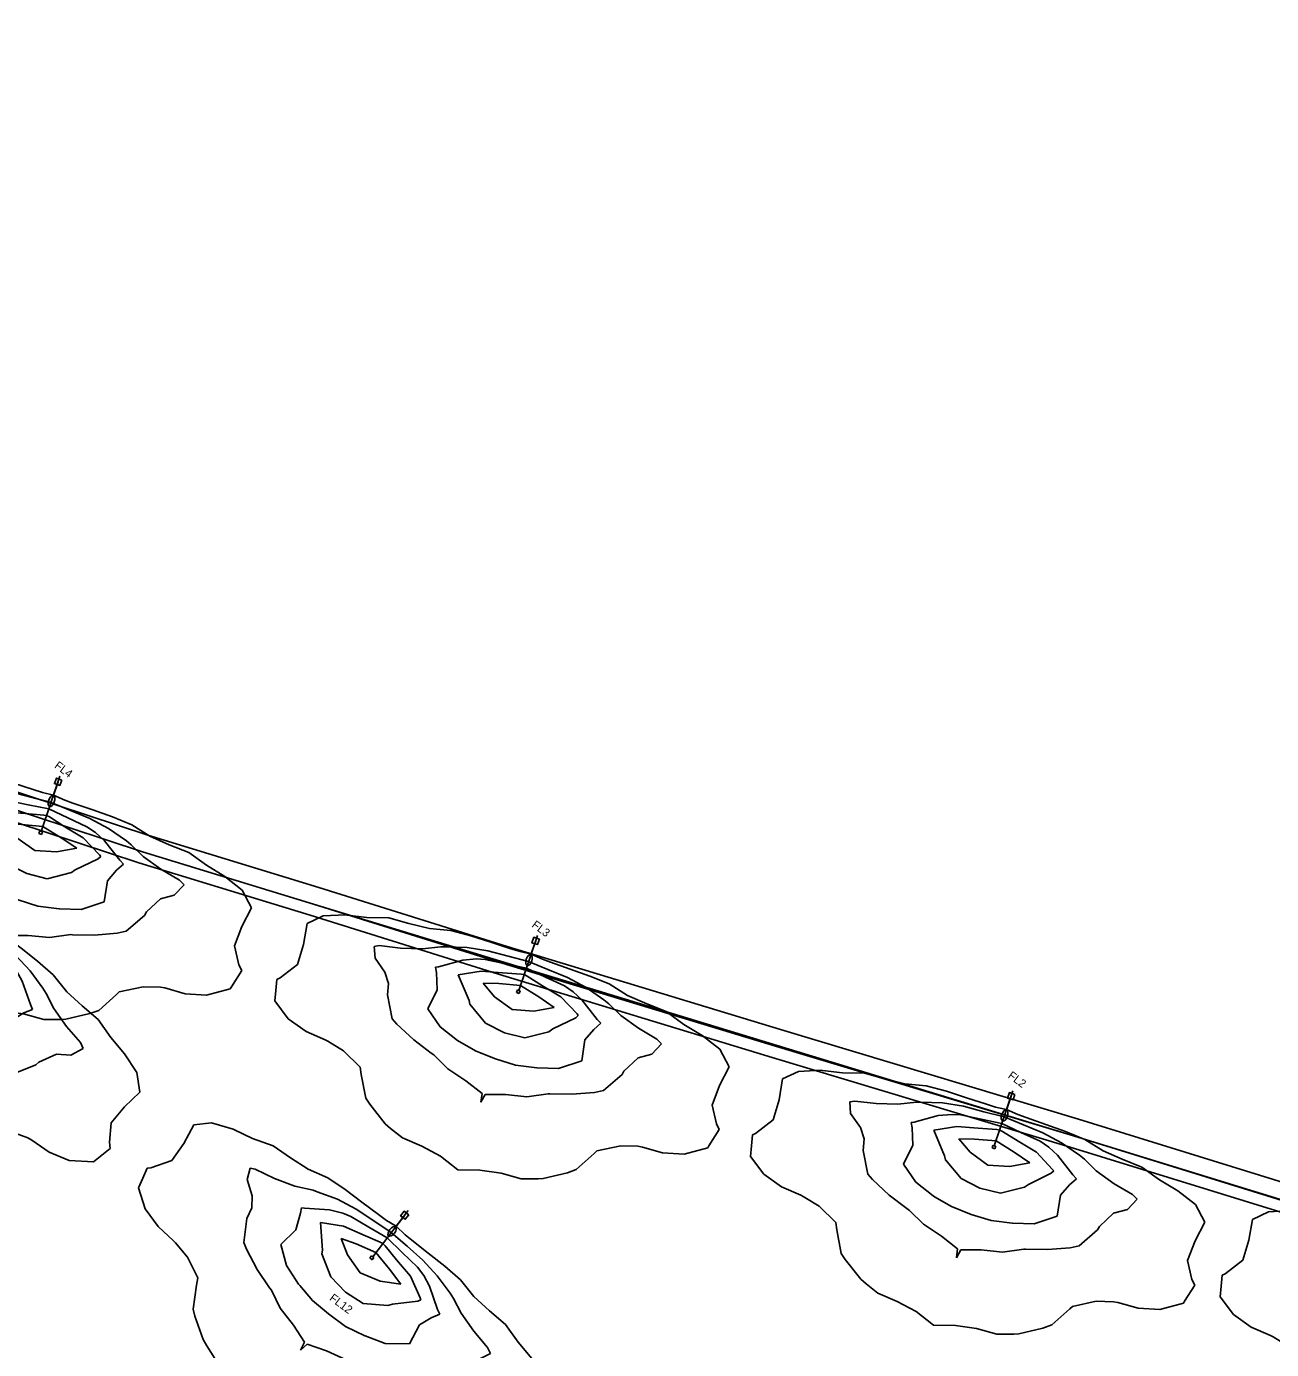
# Model space of a CAD drawing. Extents: x 1322666 to 1327584, y 458075 to 462260.
# Drawn here: x 1324729.9 to 1325158.3, y 460364.4 to 460819.6 of the extents above; entities that cross this region are included whole.
import ezdxf

# ---------------------------------------------------------------- set-up
doc = ezdxf.new("R2010")
doc.units = 0
for name, color, linetype in [('Default', 7, 'Continuous'), ('DR_P_Culvert', 7, 'Continuous'), ('DR_P_Culvert3D', 7, 'Continuous'), ('PF_X_Ground_Line', 7, 'Continuous'), ('UT_X_Misc_Cells', 7, 'Continuous')]:
    doc.layers.add(name, color=color, linetype=linetype)

# ---------------------------------------------------------------- blocks, each defined once
blk = doc.blocks.new('AGI32-IDj66arb-Project_1-LUMINAIRE-ERL2_19C330______Symbol')
at = {"layer": 'Default'}
for p, q in [((-0.03, 0), (0.03, 0)), ((0, 0.13), (0.24, 0.13)), ((0, -0.13), (0, 0.13)), ((0, 0.13), (0, 0.13)), ((0, 0.13), (0.24, 0.13)), ((0.24, 0.13), (0, 0.13)), ((0, -0.13), (0, 0.13)), ((0, 0.13), (0, 0.13)), ((0, 0.13), (0, -0.13)), ((0.24, 0.13), (0, 0.13)), ((0, 0.13), (0, -0.13)), ((0, -0.03), (0, 0.03)), ((0, 0.03), (0.03, 0)), ((0, -0.03), (0.03, 0)), ((0.24, 0.13), (0.24, -0.13)), ((0.24, 0.13), (0.24, 0.13)), ((0.24, 0.13), (0.24, 0.13)), ((0.24, 0.13), (0.24, -0.13)), ((0.24, -0.13), (0.24, 0.13)), ((0.24, -0.13), (0.24, 0.13)), ((0.24, -0.13), (0, -0.13)), ((0.24, -0.13), (0, -0.13)), ((0, -0.13), (0, -0.13)), ((0, -0.13), (0.24, -0.13)), ((0, -0.13), (0, -0.13)), ((0, -0.13), (0.24, -0.13)), ((0.24, -0.13), (0.24, -0.13)), ((0.24, -0.13), (0.24, -0.13))]:
    blk.add_line(p, q, dxfattribs=at)
blk = doc.blocks.new('AGI32-IDj66arb-Project_1-LUMINAIRE-ERL2_19C330______64-1')
at = {"layer": 'Default'}
blk.add_blockref('AGI32-IDj66arb-Project_1-LUMINAIRE-ERL2_19C330______Symbol', (0, 0), dxfattribs=at)
blk = doc.blocks.new('AGI32-IDj66arb-Project_1-LUMINAIRE-ERL2_19C330______Template1')
at = {"layer": 'Default'}
for p, q in [((9.14, 19.22), (10.58, 20.11)), ((10.58, 20.11), (10.97, 20.5)), ((10.97, 20.5), (12.6, 20.11)), ((12.6, 20.11), (12.8, 20.07)), ((12.8, 20.07), (13.99, 18.29)), ((4.29, 18.29), (5.49, 19.56)), ((5.49, 19.56), (7.31, 19.28)), ((7.31, 19.28), (9.14, 19.22)), ((3.66, 16.46), (4.29, 18.29)), ((13.99, 18.29), (14.48, 16.46)), ((3.25, 14.63), (3.66, 16.45)), ((3.66, 16.45), (3.66, 16.46)), ((14.48, 16.46), (14.57, 14.63)), ((2.69, 12.8), (3.25, 14.63)), ((14.57, 14.63), (14.63, 14.24)), ((14.63, 14.24), (15.08, 12.8)), ((2.59, 10.97), (2.69, 12.8)), ((4.85, 10.97), (5.23, 12.8)), ((5.23, 12.8), (5.49, 13.32)), ((5.49, 13.32), (6.62, 12.8)), ((6.62, 12.8), (7.31, 11.77)), ((15.08, 12.8), (16.17, 10.97)), ((7.31, 11.77), (8.8, 10.97)), ((2.44, 9.14), (2.59, 10.97)), ((4.29, 9.14), (4.85, 10.97)), ((8.8, 10.97), (9.14, 10.91)), ((9.14, 10.91), (10.97, 9.83)), ((16.17, 10.97), (16.46, 10.82)), ((16.46, 10.82), (18.29, 9.79)), ((10.97, 9.83), (11.39, 9.14)), ((18.29, 9.79), (18.8, 9.14)), ((2, 7.31), (2.44, 9.14)), ((3.66, 7.83), (4.29, 9.14)), ((11.39, 9.14), (12.17, 7.31)), ((18.8, 9.14), (19.94, 7.31)), ((1.89, 5.49), (2, 7.31)), ((2.95, 5.49), (3.47, 7.31)), ((3.47, 7.31), (3.66, 7.83)), ((4.09, 5.49), (5.27, 7.31)), ((5.27, 7.31), (5.49, 7.72)), ((5.49, 7.72), (6.19, 7.31)), ((6.19, 7.31), (7.31, 6.87)), ((7.31, 6.87), (9.14, 7.19)), ((9.14, 7.19), (10.42, 5.49)), ((12.17, 7.31), (12.76, 5.49)), ((19.94, 7.31), (20.11, 6.9)), ((20.11, 6.9), (20.59, 5.49)), ((1.86, 3.66), (1.89, 5.49)), ((2.64, 3.66), (2.95, 5.49)), ((3.66, 4.54), (4.09, 5.49)), ((4.43, 3.66), (5.39, 5.49)), ((5.39, 5.49), (5.49, 5.63)), ((5.49, 5.63), (5.75, 5.49)), ((5.75, 5.49), (7.31, 3.9)), ((10.42, 5.49), (10.97, 3.69)), ((12.76, 5.49), (12.8, 5.34)), ((12.8, 5.34), (13.64, 3.66)), ((20.59, 5.49), (20.69, 3.66)), ((1.85, 1.83), (1.86, 3.66)), ((2.53, 1.83), (2.64, 3.66)), ((3.22, 1.83), (3.42, 3.66)), ((3.42, 3.66), (3.66, 4.54)), ((4.03, 1.83), (4.43, 3.66)), ((7.31, 3.9), (7.65, 3.66)), ((7.65, 3.66), (8.83, 1.83)), ((10.97, 3.69), (10.98, 3.66)), ((10.98, 3.66), (11.36, 1.83)), ((13.64, 3.66), (14.06, 1.83)), ((20.69, 3.66), (21.05, 1.83)), ((5.05, 1.83), (5.49, 3.41)), ((5.49, 3.41), (6.36, 1.83)), ((1.83, 1.08), (1.85, 1.83)), ((2.41, 0), (2.53, 1.83)), ((3.01, 0), (3.22, 1.83)), ((3.66, 0.28), (4.03, 1.83)), ((4.62, 0), (5.05, 1.83)), ((6.36, 1.83), (6.85, 0)), ((8.83, 1.83), (8.98, 0)), ((11.36, 1.83), (11.4, 0)), ((14.06, 1.83), (14.63, 0.14)), ((21.05, 1.83), (21.63, 0)), ((1.73, 0), (1.83, 1.08)), ((3.62, 0), (3.66, 0.28)), ((14.63, 0.14), (15.4, 0)), ((1.83, -0.98), (1.73, 0)), ((1.85, -1.83), (1.83, -0.98)), ((2.55, -1.83), (2.41, 0)), ((3.25, -1.83), (3.01, 0)), ((3.66, -0.25), (3.62, 0)), ((4.07, -1.83), (3.66, -0.25)), ((5.07, -1.83), (4.62, 0)), ((6.85, 0), (6.29, -1.83)), ((8.98, 0), (8.72, -1.83)), ((11.4, 0), (11.31, -1.83)), ((14.63, -0.15), (14.04, -1.83)), ((15.4, 0), (14.63, -0.15)), ((21.63, 0), (20.99, -1.83)), ((1.88, -3.66), (1.85, -1.83)), ((2.67, -3.66), (2.55, -1.83)), ((3.47, -3.66), (3.25, -1.83)), ((4.53, -3.66), (4.07, -1.83)), ((5.49, -3.15), (5.07, -1.83)), ((6.29, -1.83), (5.49, -3.15)), ((8.72, -1.83), (7.6, -3.66)), ((11.31, -1.83), (10.97, -3.51)), ((14.04, -1.83), (13.56, -3.66)), ((20.99, -1.83), (20.7, -3.66)), ((1.89, -5.49), (1.88, -3.66)), ((2.97, -5.49), (2.67, -3.66)), ((3.66, -4.38), (3.47, -3.66)), ((4.15, -5.49), (3.66, -4.38)), ((5.49, -5.44), (4.53, -3.66)), ((7.31, -3.83), (5.49, -5.44)), ((7.6, -3.66), (7.31, -3.83)), ((10.94, -3.66), (10.29, -5.49)), ((10.97, -3.51), (10.94, -3.66)), ((13.56, -3.66), (12.8, -5.21)), ((20.7, -3.66), (20.55, -5.49)), ((2.03, -7.31), (1.89, -5.49)), ((3.54, -7.31), (2.97, -5.49)), ((5.37, -7.31), (4.15, -5.49)), ((10.29, -5.49), (9.14, -7.01)), ((12.73, -5.49), (12.12, -7.31)), ((12.8, -5.21), (12.73, -5.49)), ((20.55, -5.49), (20.11, -6.73)), ((7.31, -6.76), (5.91, -7.31)), ((9.14, -7.01), (7.31, -6.76)), ((20.11, -6.73), (19.86, -7.31)), ((2.46, -9.14), (2.03, -7.31)), ((3.66, -7.66), (3.54, -7.31)), ((4.35, -9.14), (3.66, -7.66)), ((5.49, -7.55), (5.37, -7.31)), ((5.91, -7.31), (5.49, -7.55)), ((12.12, -7.31), (11.3, -9.14)), ((19.86, -7.31), (18.68, -9.14)), ((2.61, -10.97), (2.46, -9.14)), ((4.89, -10.97), (4.35, -9.14)), ((11.3, -9.14), (10.97, -9.68)), ((18.68, -9.14), (18.29, -9.64)), ((10.97, -9.68), (9.14, -10.74)), ((18.29, -9.64), (16.46, -10.68)), ((2.71, -12.8), (2.61, -10.97)), ((5.29, -12.8), (4.89, -10.97)), ((8.15, -10.97), (7.31, -11.59)), ((9.14, -10.74), (8.15, -10.97)), ((15.87, -10.97), (14.99, -12.8)), ((16.46, -10.68), (15.87, -10.97)), ((7.31, -11.59), (6.44, -12.8)), ((3.3, -14.63), (2.71, -12.8)), ((5.49, -13.2), (5.29, -12.8)), ((6.44, -12.8), (5.49, -13.2)), ((14.99, -12.8), (14.63, -14.39)), ((3.66, -16.33), (3.3, -14.63)), ((14.6, -14.63), (14.44, -16.46)), ((14.63, -14.39), (14.6, -14.63)), ((3.68, -16.46), (3.66, -16.33)), ((4.41, -18.29), (3.68, -16.46)), ((14.44, -16.46), (13.9, -18.29)), ((5.49, -19.4), (4.41, -18.29)), ((13.9, -18.29), (12.8, -19.89)), ((7.31, -19.11), (5.49, -19.4)), ((9.14, -19.03), (7.31, -19.11)), ((10.75, -20.11), (9.14, -19.03)), ((10.97, -20.33), (10.75, -20.11)), ((11.9, -20.11), (10.97, -20.33)), ((12.8, -19.89), (11.9, -20.11))]:
    blk.add_line(p, q, dxfattribs=at)
blk = doc.blocks.new('AGI32-IDj66arb-Project_1-LUMINAIRE-ERL2_19C330______64')
at = {"layer": 'Default'}
for q in [(5.08, 0), (0, 0)]:
    blk.add_line((0, 0), q, dxfattribs=at)
for name, p in [('AGI32-IDj66arb-Project_1-LUMINAIRE-ERL2_19C330______Template1', (0, 0)), ('AGI32-IDj66arb-Project_1-LUMINAIRE-ERL2_19C330______64-1', (5.08, 0))]:
    blk.add_blockref(name, p, dxfattribs=at)

msp = doc.modelspace()

# ---------------------------------------------------------------- linework, layer by layer
at = {"layer": 'DR_P_Culvert'}
for p, q in [((1324740.8, 460559.73), (1324739.16, 460555)), ((1324905.12, 460504.99), (1324903.48, 460500.27)), ((1325068.77, 460451.53), (1325067.13, 460446.81)), ((1324860.05, 460410.61), (1324856.97, 460406.67))]:
    msp.add_line(p, q, dxfattribs=at)
for points in [[(1324742.07, 460560.34), (1324741.41, 460558.45), (1324739.52, 460559.11), (1324740.18, 460561)], [(1324906.39, 460505.61), (1324905.73, 460503.72), (1324903.85, 460504.37), (1324904.5, 460506.26)], [(1325070.04, 460452.15), (1325069.39, 460450.26), (1325067.5, 460450.91), (1325068.15, 460452.8)], [(1324861.45, 460410.78), (1324860.22, 460409.2), (1324858.64, 460410.43), (1324859.88, 460412.01)]]:
    msp.add_lwpolyline(points, close=True, dxfattribs=at)
for centre, major_axis in [((1324738.5, 460553.11), (-0.66, -1.89)), ((1324902.82, 460498.38), (-0.66, -1.89)), ((1325066.47, 460444.92), (-0.66, -1.89)), ((1324855.74, 460405.09), (-1.23, -1.58))]:
    msp.add_ellipse(centre, major_axis=major_axis, ratio=0.5, dxfattribs=at)
at = {"layer": 'DR_P_Culvert3D'}
for points in [[(1325313.61, 460381.67), (1325288.02, 460385.96), (1325265.6, 460390.72), (1325174.92, 460418.01), (1325091.91, 460443.61), (1324989.4, 460474.51), (1324895.32, 460503.04), (1324830.48, 460523.41), (1324771.61, 460541.39), (1324709.26, 460561.9), (1324667.39, 460578.33), (1324617.11, 460602.1), (1324577.13, 460624.61), (1324508.29, 460671.66), (1324466.72, 460701.28), (1324334.23, 460800.54), (1324181.37, 460915.08), (1323797.37, 461202.12), (1323665.93, 461300.42), (1323464.99, 461451.01), (1323298.56, 461579.22)], [(1325312.61, 460375.75), (1325286.9, 460380.06), (1325264.11, 460384.9), (1325173.17, 460412.27), (1325090.16, 460437.87), (1324987.66, 460468.76), (1324893.55, 460497.31), (1324828.71, 460517.68), (1324769.79, 460535.67), (1324707.22, 460556.25), (1324665.01, 460572.82), (1324614.35, 460596.77), (1324573.96, 460619.51), (1324504.85, 460666.74), (1324463.18, 460696.44), (1324330.63, 460795.74), (1324177.78, 460910.28), (1323793.78, 461197.32), (1323662.33, 461295.62), (1323461.36, 461446.23), (1323294.9, 461574.47)], [(1323292.45, 461571.3), (1323458.94, 461443.04), (1323659.93, 461292.42), (1323791.38, 461194.11), (1323928.66, 461091.5), (1324047.04, 461003.01), (1324175.38, 460907.08), (1324328.24, 460792.54), (1324460.82, 460693.21), (1324502.56, 460663.46), (1324571.84, 460616.11), (1324612.51, 460593.22), (1324663.42, 460569.15), (1324705.87, 460552.49), (1324768.59, 460531.86), (1324827.52, 460513.86), (1324892.37, 460493.49), (1324986.5, 460464.93), (1325088.99, 460434.04), (1325172, 460408.44), (1325263.12, 460381.03), (1325286.15, 460376.13), (1325311.95, 460371.8)]]:
    msp.add_lwpolyline(points, dxfattribs=at)
at = {"layer": 'PF_X_Ground_Line'}
msp.add_lwpolyline([(1325336.51, 460403.02), (1325289.49, 460388.85), (1325213.26, 460400.13), (1325090.16, 460437.87), (1324828.71, 460517.68), (1324769.79, 460535.67), (1324707.22, 460556.25), (1324665.01, 460572.82), (1324614.35, 460596.77), (1324573.96, 460619.51), (1324553.09, 460633.8), (1324504.85, 460666.74), (1324410.85, 460736.87)], dxfattribs=at)

# ---------------------------------------------------------------- block references
at = {"layer": 'DR_P_Culvert'}
for p, xscale, yscale, rotation in [((1324741.4, 460561.62), 3.9370000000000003, 3.9369999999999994, -108.74000354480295), ((1324721.09, 460517.06), 3.9370000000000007, 3.9370000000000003, -127.5957929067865), ((1324905.72, 460506.88), 3.9370000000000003, 3.9369999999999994, -108.74000354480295), ((1325069.37, 460453.42), 3.9370000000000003, 3.9369999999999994, -108.74000354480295), ((1324861.23, 460412.2), 3.9370000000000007, 3.9370000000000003, -127.5957929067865), ((1325231.01, 460405.12), 3.9370000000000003, 3.9369999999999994, -108.74000354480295)]:
    msp.add_blockref('AGI32-IDj66arb-Project_1-LUMINAIRE-ERL2_19C330______64', p, dxfattribs=dict(at, xscale=xscale, yscale=yscale, rotation=rotation))

# ---------------------------------------------------------------- texts
at = {"layer": 'UT_X_Misc_Cells'}
for s, p in [('FL4', (1324739.28, 460564.76)), ('FL3', (1324903.54, 460510)), ('FL2', (1325067.4, 460458.12)), ('FL12', (1324833.91, 460381.59))]:
    msp.add_text(s, height=2.8, rotation=323.4759, dxfattribs=at).set_placement(p)

doc.saveas('drawing.dxf')
